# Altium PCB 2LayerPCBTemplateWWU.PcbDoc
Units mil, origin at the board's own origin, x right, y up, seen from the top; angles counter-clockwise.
Board outline 716.1 x 716.1 mil, 2 copper layers (Top Layer, Bottom Layer); 11 components, 9 nets, 28 pads, 2 vias.
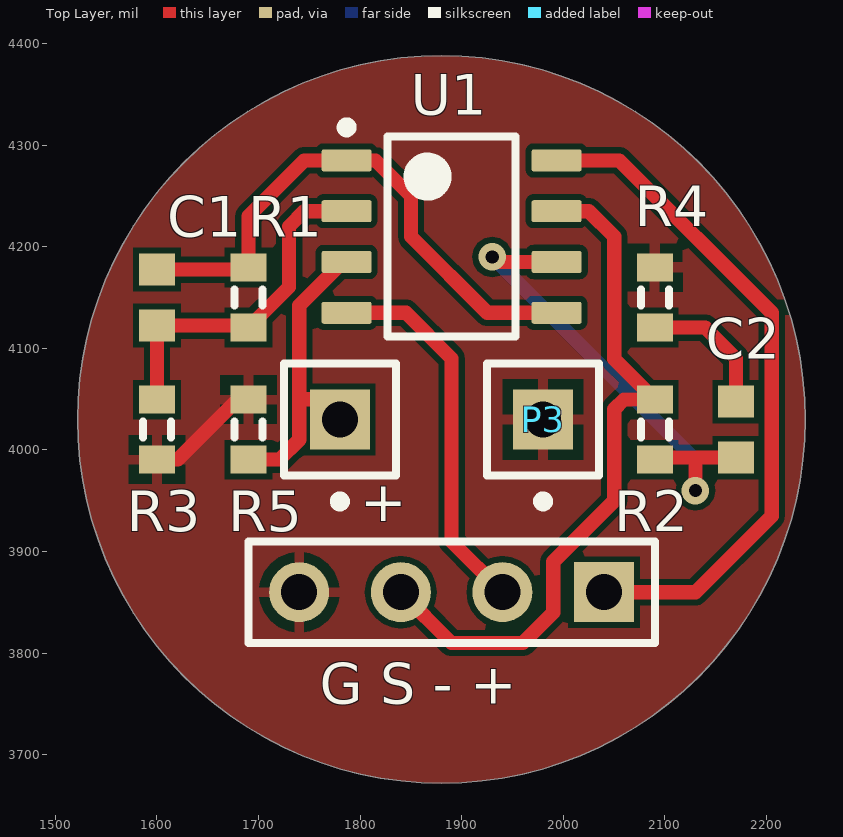
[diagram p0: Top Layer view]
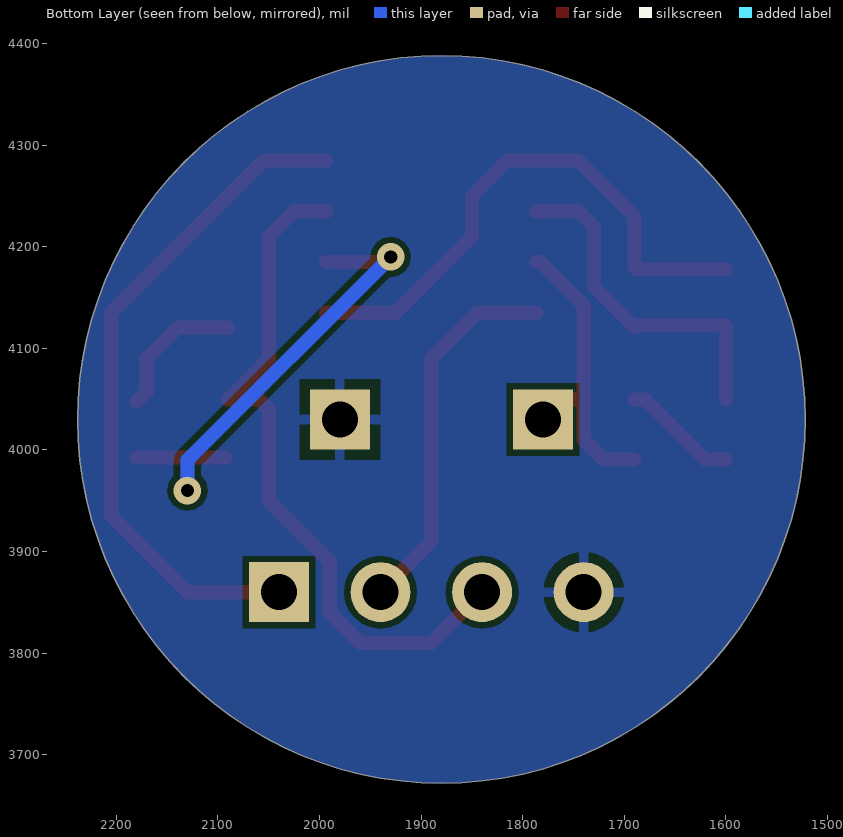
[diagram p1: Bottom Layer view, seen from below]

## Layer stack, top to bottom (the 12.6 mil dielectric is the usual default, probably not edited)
Top Solder: solder mask 0.4, Solder Resist, Dk 3.5
Top Layer: signal copper 1.4
Dielectric 1: dielectric 12.6, FR-4, Dk 4.8
Bottom Layer: signal copper 1.4
Bottom Solder: solder mask 0.4, Solder Resist, Dk 3.5

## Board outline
1880,3671.95 cw(c1880,4030) 1521.95,4030 cw(c1880,4030) 1880,4388.05 cw(c1880,4030) 2238.05,4030 cw(c1880,4030)

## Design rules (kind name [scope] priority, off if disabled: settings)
Clearance [All] p1: gap=6
HoleSize [All] p1: absolutevalues=TRUE maxlimit=125 minlimit=13 maxpercent=80.000 minpercent=20.000
MinimumSolderMaskSliver [All] p1: minsoldermaskwidth=1
PolygonConnect [All] p1: connectstyle=Relief reliefconductorwidth=10 reliefentries=4 polygonreliefangle="90 Angle" airgapwidth=10
RoutingVias [All] p1: holewidth=13 width=20 viastyle="Through Hole" minholewidth=13 minwidth=20 maxholewidth=125 maxwidth=250
SilkToSilkClearance [All] p1: silktosilkclearance=4
SilkToSolderMaskClearance [IsPad] p1: minsilkscreentomaskgap=6 clearancetoexposedcopper=TRUE
SolderMaskExpansion [All] p1: expansion=4
UnpouredPolygon [All] p1: allowunpoured=FALSE
Width [All] p1: maxlimit=500 minlimit=6 preferedwidth=25
25 further rules are at their usual default settings.

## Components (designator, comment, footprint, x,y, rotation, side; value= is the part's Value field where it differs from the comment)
+ "Plug" PIN1 1780,4030 r180 top (schematic designator P2)
C1 "Cap Semi" 1608[0603] 1600,4150 r90 top
C2 "Cap Semi" 1608[0603] 2170,4020 r270 top
"G S - +" "Header 4" HDR1X4 2040,3860 r180 top (schematic designator P1)
P3 "Plug" PIN1 1980,4030 r180 top
R1 "Res3" J1-0603 1690,4150 r270 top
R2 "Res3" J1-0603 2090,4020 r270 top
R3 "Res3" J1-0603 1600,4020 r270 top
R4 "Res3" J1-0603 2090,4150 r90 top
R5 "Res3" J1-0603 1690,4020 r270 top
U1 "LF353M/NOPB" D0008A_L 1890,4210 r0 top

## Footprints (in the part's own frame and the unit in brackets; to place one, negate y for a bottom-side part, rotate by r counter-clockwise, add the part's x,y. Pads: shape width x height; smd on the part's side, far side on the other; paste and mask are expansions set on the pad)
1608[0603] [mm] "Chip Capacitor, Body 1.6x0.8mm, IPC High Density"
  rect 0.8x0.9 smd: 1(-0.7,0) 2(0.7,0)
  body extent -0.87,-0.48 0.87,0.48, height 1.3
D0008A_L [mm] "SOIC, 8-Leads, Body 5x4mm, Pitch 1.27mm, IPC High Density"
  rrect18% 1.25x0.55 smd: 1(-2.625,1.905) 2(-2.625,0.635) 3(-2.625,-0.635) 4(-2.625,-1.905) 5(2.625,-1.905) 6(2.625,-0.635) 7(2.625,0.635) 8(2.625,1.905)
  silkscreen extent -2.75,-2.5 1.6,2.85, body extent -3,-2.45 3,2.45, height 1.63
HDR1X4 [mm] "Connector; Header; 4 Position"
  rect 1.5x1.5 hole 0.9: 1(0,0)
  round 1.5 hole 0.9: 2(2.54,0) 3(5.08,0) 4(7.62,0)
  silkscreen extent -1.27,-1.27 8.89,1.27
J1-0603 [mm] "Chip Resistor, Body 1.6x0.8mm, IPC High Density"
  rect 0.7x0.9 smd: 1(-0.75,0) 2(0.75,0)
  silkscreen extent -0.2,-0.35 0.2,0.35, body extent -0.85,-0.48 0.85,0.48, height 0.9
PIN1 [mm] "Connector; Plug"
  rect 1.5x1.5 hole 0.9: 1(0,0)
  silkscreen extent -1.4,-1.4 1.4,2.17

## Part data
C1 C2: "Capacitor (Semiconductor SIM Model)"
"G S - +": "Header, 4-Pin"
R1 R2 R3 R4 R5: "Resistor"
U1: library part CMP-0055-00856-3, "Wide Bandwidth Dual JFET Input Operational Amplifier, 8-pin Narrow SOIC, Pb-Free"

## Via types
v1: diameter 27, hole 13, Top Layer to Bottom Layer, tented both sides, 2 vias

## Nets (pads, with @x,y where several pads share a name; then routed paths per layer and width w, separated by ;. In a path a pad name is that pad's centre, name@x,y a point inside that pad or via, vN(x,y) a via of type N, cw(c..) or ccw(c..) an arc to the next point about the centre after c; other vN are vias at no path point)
+12V: "G S - +.1" U1.8 | length 669.9
  Top Layer w14: U1.8 2055,4285 2205,4135 2205,3935 2130,3860 2040,3860
-12V: "G S - +.2" U1.4 | length 372.7
  Top Layer w14: U1.4 1845,4135 1890,4090 1890,3910 1940,3860
MIC+: +.1 R5.2 U1.3 | length 318.8
  Top Layer w14: R5.2 1720.47,3990.47 1740,4010 1740,4050 ; U1.3 1782.81,4185 1740,4142.19 1740,4050 ; +.1@1800,4040 1790,4050 1740,4050
MIC-: "G S - +.4" P3.1 R3.2 R4.2 R5.1 | length 114.5
  Top Layer w14: R3.2 1620.47,3990.47 1679.53,4049.53 R5.1
NetC1_1: C1.1 R1.2 R3.1 U1.2 | length 343.8
  Top Layer w14: R3.1 C1.1 R1.2@1691.97,4122.44 ; R1.2 R1.2@1691.97,4122.44 ; U1.2 1745,4235 1730,4220 1730,4160.47 R1.2@1691.97,4122.44
NetC1_2: C1.2 R1.1 U1.1 U1.5 | length 550.2
  Top Layer w14: C1.2 R1.1@1688.03,4177.56 ; R1.1 1690,4230 1745,4285 U1.1 1815,4285 1850,4250 1850,4210 1925,4135 U1.5
NetC2_1: C2.1 R4.1 | length 139.2
  Top Layer w14: R4.1 2139.53,4120.47 2170,4090 2170,4057.56 C2.1@2180,4047.56
NetC2_2: C2.2 R2.2 U1.6 | length 498.7
  Top Layer w14: v1(1930,4190) 1935,4185 U1.6 ; R2.2@2091.97,3992.44 2130,3992.44 ; v1(2130,3960) 2130,3992.44 ; C2.2@2180,3992.44 2130,3992.44
  Bottom Layer w14: v1(1930,4190) 2130,3990 v1(2130,3960)
SIG_OUT: "G S - +.3" R2.1 U1.7 | length 696
  Top Layer w14: 1840,3860 1890,3810 1960,3810 1990,3840 1990,3890 2050,3950 2050,4040 2059.53,4049.53 R2.1 2050,4089.53 2050,4210 2025,4235 U1.7

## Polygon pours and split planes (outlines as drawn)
MIC- on Top Layer "GND" (solid, pour order 5): 1880,3671.95 cw(c1880,4030) 1521.95,4030 cw(c1880,4030) 1880,4388.05 cw(c1880,4030) 2238.05,4030 cw(c1880,4030)
MIC- on Bottom Layer "GND" (solid, pour order 6): 1880,3671.95 cw(c1880,4030) 1521.95,4030 cw(c1880,4030) 1880,4388.05 cw(c1880,4030) 2238.05,4030 cw(c1880,4030)

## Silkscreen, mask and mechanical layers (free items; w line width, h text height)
Mechanical 3:
  circle w10: c1880,4030 r358.05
